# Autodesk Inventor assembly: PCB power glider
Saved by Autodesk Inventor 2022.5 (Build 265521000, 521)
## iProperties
Created: 2025-02
Part Number: PCB power glider
Document SubType Name: Assembly
Designer: AdminForWorker
Title: PCB power glider v5
Author: AdminForWorker
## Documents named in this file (6)
- c:\worker\convert-fusion-r06-cosv3\tmp\job-1\156\temp\files\4da247ac-f9c9-4f90-bd24-12f2ccf5ab43\47d7c64a-0e39-44a0-ae7d-0fcd95337212.iam
- c:\worker\convert-fusion-r06-cosv3\tmp\job-1\156\temp\files\4da247ac-f9c9-4f90-bd24-12f2ccf5ab43\Board.ipt
- c:\worker\convert-fusion-r06-cosv3\tmp\job-1\156\temp\files\4da247ac-f9c9-4f90-bd24-12f2ccf5ab43\1-copper.ipt
- c:\worker\convert-fusion-r06-cosv3\tmp\job-1\156\temp\files\4da247ac-f9c9-4f90-bd24-12f2ccf5ab43\16-copper.ipt
- c:\worker\convert-fusion-r06-cosv3\tmp\job-1\156\temp\files\4da247ac-f9c9-4f90-bd24-12f2ccf5ab43\1-soldermask.ipt
- c:\worker\convert-fusion-r06-cosv3\tmp\job-1\156\temp\files\4da247ac-f9c9-4f90-bd24-12f2ccf5ab43\16-soldermask.ipt
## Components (5 placed, 5 different names)
1. Board:1
2. 1-copper:1
3. 16-copper:1
4. 1-soldermask:1
5. 16-soldermask:1
